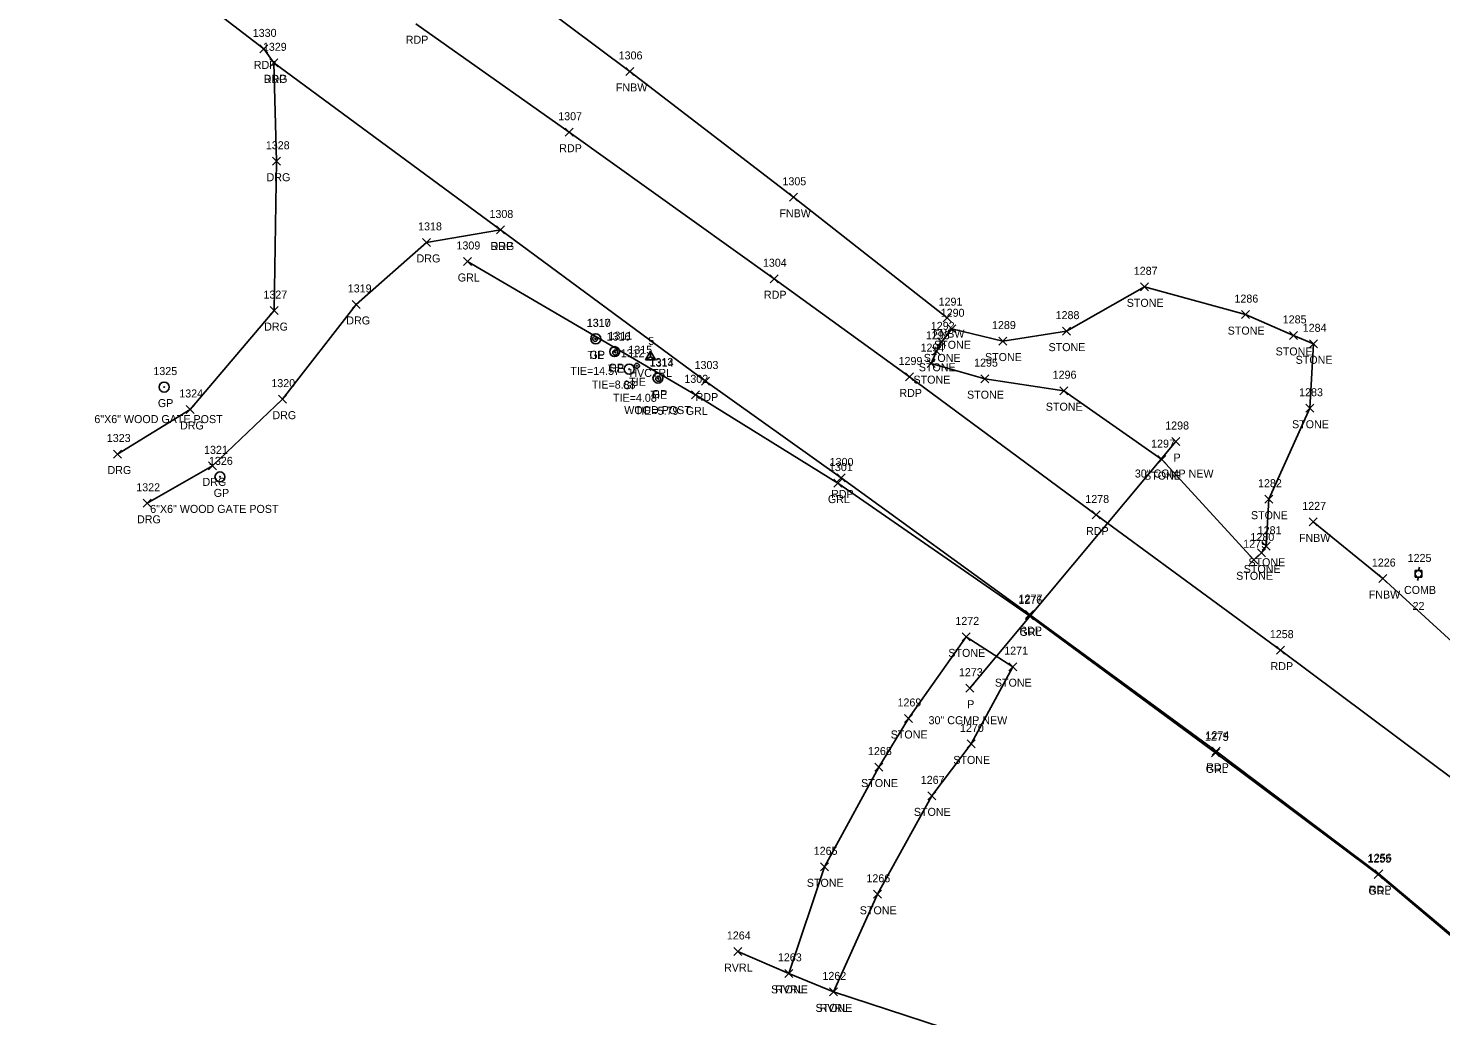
# Model space of a CAD drawing. Extents: x 1503463 to 1505240, y 712171 to 717196.
# Drawn here: x 1503951.4 to 1504304.4, y 715100.2 to 715346.9 of the extents above; entities that cross this region are included whole.
import ezdxf

# ---------------------------------------------------------------- set-up
doc = ezdxf.new("R2010")
doc.units = 0
for name, color, linetype in [('C_A', 7, 'Continuous'), ('C_C', 7, 'Continuous'), ('C_I', 7, 'Continuous'), ('CBP', 7, 'Continuous'), ('CPSM', 7, 'Continuous'), ('D_A', 7, 'Continuous'), ('D_C', 7, 'Continuous'), ('D_I', 7, 'Continuous'), ('D_TIC', 7, 'Continuous'), ('DCP', 7, 'Continuous'), ('L_A', 7, 'Continuous'), ('L_I', 7, 'Continuous'), ('L_TIC', 7, 'Continuous'), ('LASF', 7, 'Continuous'), ('LAWE', 7, 'Continuous'), ('LFNC', 7, 'Continuous'), ('P_A', 7, 'Continuous'), ('P_I', 7, 'Continuous'), ('P_TIC', 7, 'Continuous'), ('PET', 7, 'Continuous'), ('R_A', 7, 'Continuous'), ('R_C', 7, 'Continuous'), ('R_I', 7, 'Continuous'), ('R_TIC', 7, 'Continuous'), ('RDG', 7, 'Continuous'), ('RGP', 7, 'Continuous'), ('RGR', 7, 'Continuous'), ('U_A', 7, 'Continuous'), ('U_C', 7, 'Continuous'), ('U_I', 7, 'Continuous'), ('UP', 7, 'Continuous')]:
    doc.layers.add(name, color=color, linetype=linetype)

msp = doc.modelspace()

# ---------------------------------------------------------------- linework, layer by layer
at = {"layer": 'CBP'}
for centre, radius in [((1504093.06, 715269.34), 0.625), ((1504093.06, 715269.34), 0.0833), ((1504098.1, 715265.92), 0.625), ((1504098.1, 715265.92), 0.0833), ((1504103.49, 715262.61), 0.625), ((1504103.49, 715262.61), 0.0833), ((1504108.84, 715259.36), 0.625), ((1504108.84, 715259.36), 0.0833)]:
    msp.add_circle(centre, radius, dxfattribs=at)
at = {"layer": 'CPSM'}
for p, q in [((1504105.67, 715264.1), (1504106.92, 715266.27)), ((1504105.67, 715264.1), (1504106.92, 715264.82)), ((1504105.67, 715264.1), (1504108.17, 715264.1)), ((1504108.17, 715264.1), (1504106.92, 715266.27)), ((1504106.92, 715264.82), (1504106.92, 715266.27)), ((1504106.92, 715264.82), (1504106.92, 715264.82)), ((1504106.92, 715264.82), (1504108.17, 715264.1))]:
    msp.add_line(p, q, dxfattribs=at)
at = {"layer": 'D_TIC'}
for points in [[(1504237.24, 715242.69), (1504239.24, 715244.69)], [(1504239.24, 715242.69), (1504237.24, 715244.69)], [(1504185.69, 715181.05), (1504187.69, 715183.05)], [(1504187.69, 715181.05), (1504185.69, 715183.05)]]:
    msp.add_lwpolyline(points, dxfattribs=at)
at = {"layer": 'DCP'}
msp.add_lwpolyline([(1504186.69, 715182.05), (1504238.24, 715243.69)], dxfattribs=at)
at = {"layer": 'L_TIC'}
for points in [[(1504100.77, 715335.16), (1504102.77, 715337.16)], [(1504102.77, 715335.16), (1504100.77, 715337.16)], [(1504141.65, 715303.71), (1504143.65, 715305.71)], [(1504143.65, 715303.71), (1504141.65, 715305.71)], [(1504229.38, 715281.34), (1504231.38, 715283.34)], [(1504231.38, 715281.34), (1504229.38, 715283.34)], [(1504180.03, 715273.63), (1504182.03, 715275.63)], [(1504182.03, 715273.63), (1504180.03, 715275.63)], [(1504254.61, 715274.4), (1504256.61, 715276.4)], [(1504256.61, 715274.4), (1504254.61, 715276.4)], [(1504181.22, 715270.86), (1504183.22, 715272.86)], [(1504183.22, 715270.86), (1504181.22, 715272.86)], [(1504209.85, 715270.27), (1504211.85, 715272.27)], [(1504211.85, 715270.27), (1504209.85, 715272.27)], [(1504266.61, 715269.2), (1504268.61, 715271.2)], [(1504268.61, 715269.2), (1504266.61, 715271.2)], [(1504177.42, 715265.24), (1504179.42, 715267.24)], [(1504179.42, 715265.24), (1504177.42, 715267.24)], [(1504178.65, 715267.58), (1504180.65, 715269.58)], [(1504180.65, 715267.58), (1504178.65, 715269.58)], [(1504193.96, 715267.79), (1504195.96, 715269.79)], [(1504195.96, 715267.79), (1504193.96, 715269.79)], [(1504271.61, 715267.1), (1504273.61, 715269.1)], [(1504273.61, 715267.1), (1504271.61, 715269.1)], [(1504176.09, 715262.15), (1504178.09, 715264.15)], [(1504178.09, 715262.15), (1504176.09, 715264.15)], [(1504189.48, 715258.39), (1504191.48, 715260.39)], [(1504191.48, 715258.39), (1504189.48, 715260.39)], [(1504209.17, 715255.38), (1504211.17, 715257.38)], [(1504211.17, 715255.38), (1504209.17, 715257.38)], [(1504270.71, 715251), (1504272.71, 715253)], [(1504272.71, 715251), (1504270.71, 715253)], [(1504233.72, 715238.16), (1504235.72, 715240.16)], [(1504235.72, 715238.16), (1504233.72, 715240.16)], [(1504233.72, 715238.16), (1504235.72, 715240.16)], [(1504235.72, 715238.16), (1504233.72, 715240.16)], [(1504260.44, 715228.28), (1504262.44, 715230.28)], [(1504262.44, 715228.28), (1504260.44, 715230.28)], [(1504271.51, 715222.61), (1504273.51, 715224.61)], [(1504273.51, 715222.61), (1504271.51, 715224.61)], [(1504259.79, 715216.52), (1504261.79, 715218.52)], [(1504261.79, 715216.52), (1504259.79, 715218.52)], [(1504256.74, 715213.14), (1504258.74, 715215.14)], [(1504258.74, 715213.14), (1504256.74, 715215.14)], [(1504256.74, 715213.14), (1504258.74, 715215.14)], [(1504258.74, 715213.14), (1504256.74, 715215.14)], [(1504258.64, 715214.84), (1504260.64, 715216.84)], [(1504260.64, 715214.84), (1504258.64, 715216.84)], [(1504288.94, 715208.45), (1504290.94, 715210.45)], [(1504290.94, 715208.45), (1504288.94, 715210.45)], [(1504184.8, 715193.87), (1504186.8, 715195.87)], [(1504186.8, 715193.87), (1504184.8, 715195.87)], [(1504184.8, 715193.87), (1504186.8, 715195.87)], [(1504186.8, 715193.87), (1504184.8, 715195.87)], [(1504196.44, 715186.43), (1504198.44, 715188.43)], [(1504198.44, 715186.43), (1504196.44, 715188.43)], [(1504170.38, 715173.49), (1504172.38, 715175.49)], [(1504172.38, 715173.49), (1504170.38, 715175.49)], [(1504186.04, 715167.13), (1504188.04, 715169.13)], [(1504188.04, 715167.13), (1504186.04, 715169.13)], [(1504163, 715161.35), (1504165, 715163.35)], [(1504165, 715161.35), (1504163, 715163.35)], [(1504176.19, 715154.15), (1504178.19, 715156.15)], [(1504178.19, 715154.15), (1504176.19, 715156.15)], [(1504149.43, 715136.42), (1504151.43, 715138.42)], [(1504151.43, 715136.42), (1504149.43, 715138.42)], [(1504162.66, 715129.56), (1504164.66, 715131.56)], [(1504164.66, 715129.56), (1504162.66, 715131.56)], [(1504127.72, 715115.26), (1504129.72, 715117.26)], [(1504129.72, 715115.26), (1504127.72, 715117.26)], [(1504140.48, 715109.8), (1504142.48, 715111.8)], [(1504142.48, 715109.8), (1504140.48, 715111.8)], [(1504140.48, 715109.8), (1504142.48, 715111.8)], [(1504142.48, 715109.8), (1504140.48, 715111.8)], [(1504151.61, 715105.17), (1504153.61, 715107.17)], [(1504153.61, 715105.17), (1504151.61, 715107.17)], [(1504151.61, 715105.17), (1504153.61, 715107.17)], [(1504153.61, 715105.17), (1504151.61, 715107.17)]]:
    msp.add_lwpolyline(points, dxfattribs=at)
at = {"layer": 'LASF'}
for points in [[(1504257.74, 715214.14), (1504259.64, 715215.84), (1504260.79, 715217.52), (1504261.44, 715229.28), (1504271.71, 715252), (1504272.61, 715268.1), (1504267.61, 715270.2), (1504255.61, 715275.4), (1504230.38, 715282.34), (1504210.85, 715271.27), (1504194.96, 715268.79), (1504182.22, 715271.86), (1504179.65, 715268.58), (1504178.42, 715266.24), (1504177.09, 715263.15), (1504190.48, 715259.39), (1504210.17, 715256.38), (1504234.72, 715239.16)], [(1504257.74, 715214.14), (1504234.72, 715239.16)], [(1504141.48, 715110.8), (1504150.43, 715137.42), (1504164, 715162.35), (1504171.38, 715174.49), (1504185.8, 715194.87)], [(1504152.61, 715106.17), (1504163.66, 715130.56), (1504177.19, 715155.15), (1504187.04, 715168.13), (1504197.44, 715187.43), (1504185.8, 715194.87)]]:
    msp.add_lwpolyline(points, dxfattribs=at)
at = {"layer": 'LAWE'}
msp.add_lwpolyline([(1504428.01, 714856.32), (1504405.57, 714893.54), (1504378.11, 714927.51), (1504347.53, 714961.21), (1504311.78, 715002.92), (1504271.16, 715045.67), (1504223.13, 715076), (1504189.07, 715094.24), (1504152.61, 715106.17), (1504141.48, 715110.8), (1504128.72, 715116.26)], dxfattribs=at)
at = {"layer": 'LFNC'}
for points in [[(1504181.03, 715274.63), (1504142.65, 715304.71), (1504101.77, 715336.16), (1504063.51, 715364.82), (1504042.83, 715378.65)], [(1504574.09, 714914.16), (1504555.66, 714950.38), (1504537.29, 714983.75), (1504525.24, 715002.94), (1504507.14, 715023.01), (1504480.75, 715051.19), (1504465.15, 715069.97), (1504427.46, 715093.92), (1504393.83, 715121.36), (1504359.79, 715149.8), (1504312.1, 715189.24), (1504289.94, 715209.45), (1504272.51, 715223.61)]]:
    msp.add_lwpolyline(points, dxfattribs=at)
at = {"layer": 'P_TIC'}
for points in [[(1504009.26, 715340.79), (1504011.26, 715342.79)], [(1504011.26, 715340.79), (1504009.26, 715342.79)], [(1504011.71, 715337.31), (1504013.71, 715339.31)], [(1504013.71, 715337.31), (1504011.71, 715339.31)], [(1504085.6, 715319.97), (1504087.6, 715321.97)], [(1504087.6, 715319.97), (1504085.6, 715321.97)], [(1504068.42, 715295.54), (1504070.42, 715297.54)], [(1504070.42, 715295.54), (1504068.42, 715297.54)], [(1504136.77, 715283.36), (1504138.77, 715285.36)], [(1504138.77, 715283.36), (1504136.77, 715285.36)], [(1504170.61, 715258.82), (1504172.61, 715260.82)], [(1504172.61, 715258.82), (1504170.61, 715260.82)], [(1504119.68, 715257.8), (1504121.68, 715259.8)], [(1504121.68, 715257.8), (1504119.68, 715259.8)], [(1504153.53, 715233.59), (1504155.53, 715235.59)], [(1504155.53, 715233.59), (1504153.53, 715235.59)], [(1504217.27, 715224.33), (1504219.27, 715226.33)], [(1504219.27, 715224.33), (1504217.27, 715226.33)], [(1504200.61, 715199.45), (1504202.61, 715201.45)], [(1504202.61, 715199.45), (1504200.61, 715201.45)], [(1504263.39, 715190.56), (1504265.39, 715192.56)], [(1504265.39, 715190.56), (1504263.39, 715192.56)], [(1504247.31, 715165.3), (1504249.31, 715167.3)], [(1504249.31, 715165.3), (1504247.31, 715167.3)], [(1504287.97, 715134.69), (1504289.97, 715136.69)], [(1504289.97, 715134.69), (1504287.97, 715136.69)]]:
    msp.add_lwpolyline(points, dxfattribs=at)
at = {"layer": 'PET'}
for points in [[(1504628.86, 714571.69), (1504621.33, 714603.22), (1504611.21, 714644.87), (1504597.35, 714691.39), (1504582.78, 714732.74), (1504571.53, 714760.83), (1504551.13, 714806.83), (1504531.24, 714845.96), (1504513.33, 714878.02), (1504484.92, 714923.88), (1504464.76, 714952.16), (1504434.64, 714992.6), (1504400.79, 715031.63), (1504363.93, 715069.91), (1504326.41, 715104.24), (1504288.97, 715135.69), (1504248.31, 715166.3), (1504201.61, 715200.45), (1504154.53, 715234.59), (1504120.68, 715258.8), (1504069.42, 715296.54), (1504012.71, 715338.31), (1504010.26, 715341.79), (1503951.37, 715387.03)], [(1504657.14, 714577.6), (1504649.31, 714613.48), (1504639.83, 714651.58), (1504624, 714703.83), (1504610.47, 714743.63), (1504599.62, 714771.44), (1504577.65, 714820.8), (1504557.24, 714860.24), (1504539.4, 714891.39), (1504508.82, 714940.05), (1504488.73, 714969.22), (1504457.88, 715009.77), (1504422.56, 715051.33), (1504384.13, 715091.33), (1504346.68, 715126.54), (1504308.22, 715158.84), (1504264.39, 715191.56), (1504218.27, 715225.33), (1504171.61, 715259.82), (1504137.77, 715284.36), (1504086.6, 715320.97), (1504048.23, 715348.08)]]:
    msp.add_lwpolyline(points, dxfattribs=at)
at = {"layer": 'R_TIC'}
for points in [[(1504011.71, 715337.31), (1504013.71, 715339.31)], [(1504013.71, 715337.31), (1504011.71, 715339.31)], [(1504012.44, 715312.72), (1504014.44, 715314.72)], [(1504014.44, 715312.72), (1504012.44, 715314.72)], [(1504068.42, 715295.54), (1504070.42, 715297.54)], [(1504070.42, 715295.54), (1504068.42, 715297.54)], [(1504049.93, 715292.44), (1504051.93, 715294.44)], [(1504051.93, 715292.44), (1504049.93, 715294.44)], [(1504060.18, 715287.67), (1504062.18, 715289.67)], [(1504062.18, 715287.67), (1504060.18, 715289.67)], [(1504032.37, 715276.94), (1504034.37, 715278.94)], [(1504034.37, 715276.94), (1504032.37, 715278.94)], [(1504011.84, 715275.4), (1504013.84, 715277.4)], [(1504013.84, 715275.4), (1504011.84, 715277.4)], [(1504117.14, 715254.35), (1504119.14, 715256.35)], [(1504119.14, 715254.35), (1504117.14, 715256.35)], [(1504013.91, 715253.27), (1504015.91, 715255.27)], [(1504015.91, 715253.27), (1504013.91, 715255.27)], [(1503990.81, 715250.7), (1503992.81, 715252.7)], [(1503992.81, 715250.7), (1503990.81, 715252.7)], [(1503972.69, 715239.56), (1503974.69, 715241.56)], [(1503974.69, 715239.56), (1503972.69, 715241.56)], [(1503996.43, 715236.61), (1503998.43, 715238.61)], [(1503998.43, 715236.61), (1503996.43, 715238.61)], [(1504152.7, 715232.3), (1504154.7, 715234.3)], [(1504154.7, 715232.3), (1504152.7, 715234.3)], [(1503980.06, 715227.25), (1503982.06, 715229.25)], [(1503982.06, 715227.25), (1503980.06, 715229.25)], [(1504200.6, 715199.12), (1504202.6, 715201.12)], [(1504202.6, 715199.12), (1504200.6, 715201.12)], [(1504247.14, 715164.9), (1504249.14, 715166.9)], [(1504249.14, 715164.9), (1504247.14, 715166.9)], [(1504287.79, 715134.46), (1504289.79, 715136.46)], [(1504289.79, 715134.46), (1504287.79, 715136.46)]]:
    msp.add_lwpolyline(points, dxfattribs=at)
at = {"layer": 'RDG'}
for points in [[(1503973.69, 715240.56), (1503991.81, 715251.7), (1504012.84, 715276.4), (1504013.44, 715313.72), (1504012.71, 715338.31)], [(1504069.42, 715296.54), (1504050.93, 715293.44), (1504033.37, 715277.94), (1504014.91, 715254.27), (1503997.43, 715237.61), (1503981.06, 715228.25)]]:
    msp.add_lwpolyline(points, dxfattribs=at)
at = {"layer": 'RGP'}
for p, q in [((1504093.22, 715269.35), (1504093.22, 715269.35)), ((1504097.95, 715266.14), (1504097.95, 715266.14)), ((1504101.58, 715261.76), (1504101.58, 715261.76)), ((1503985.33, 715257.29), (1503985.33, 715257.29)), ((1504108.76, 715259.54), (1504108.76, 715259.54)), ((1503999.29, 715234.85), (1503999.29, 715234.85))]:
    msp.add_line(p, q, dxfattribs=at)
for centre, radius in [((1504093.22, 715269.35), 1.25), ((1504093.22, 715269.35), 0.0833), ((1504097.95, 715266.14), 1.25), ((1504097.95, 715266.14), 0.0833), ((1504101.58, 715261.76), 1.25), ((1504101.58, 715261.76), 0.0833), ((1504108.76, 715259.54), 1.25), ((1503985.33, 715257.29), 1.25), ((1503985.33, 715257.29), 0.0833), ((1504108.76, 715259.54), 0.0833), ((1503999.29, 715234.85), 1.25), ((1503999.29, 715234.85), 0.0833)]:
    msp.add_circle(centre, radius, dxfattribs=at)
at = {"layer": 'RGR'}
msp.add_lwpolyline([(1504616.71, 714600.2), (1504618.77, 714605.75), (1504618.48, 714611.67), (1504610.41, 714644.61), (1504596.35, 714690.53), (1504582.15, 714732.64), (1504570.9, 714760.4), (1504550.39, 714806.66), (1504530.74, 714845.7), (1504512.79, 714877.73), (1504484.33, 714923.22), (1504464.3, 714951.66), (1504433.51, 714991.73), (1504399.75, 715031.08), (1504363.28, 715069.4), (1504326.1, 715103.99), (1504288.79, 715135.46), (1504248.14, 715165.9), (1504201.6, 715200.12), (1504153.7, 715233.3), (1504118.14, 715255.35), (1504061.18, 715288.67)], dxfattribs=at)
at = {"layer": 'UP'}
for p, q in [((1504298.01, 715209.77), (1504298.01, 715211.43)), ((1504298.01, 715211.43), (1504299.68, 715211.43)), ((1504299.1, 715212.27), (1504298.85, 715211.43)), ((1504298.85, 715210.6), (1504298.85, 715210.6)), ((1504299.68, 715211.43), (1504299.68, 715209.77)), ((1504299.68, 715209.77), (1504298.01, 715209.77)), ((1504298.6, 715208.93), (1504298.85, 715209.77))]:
    msp.add_line(p, q, dxfattribs=at)
msp.add_circle((1504298.85, 715210.6), 0.833, dxfattribs=at)

# ---------------------------------------------------------------- texts
at = {"layer": 'C_A'}
for s, p in [('TIE', (1504091.14, 715264.34)), ('TIE', (1504096.18, 715260.92)), ('HVCTRL', (1504101.61, 715259.82)), ('TIE', (1504101.57, 715257.61)), ('TIE', (1504106.92, 715254.36))]:
    msp.add_text(s, height=2, dxfattribs=at).set_placement(p)
at = {"layer": 'C_C'}
for s, p in [('TIE=14.57', (1504086.86, 715260.34)), ('TIE=8.88', (1504092.23, 715256.92)), ('TIE=4.08', (1504097.53, 715253.61)), ('TIE=5.79', (1504102.96, 715250.36))]:
    msp.add_text(s, height=2, dxfattribs=at).set_placement(p)
at = {"layer": 'C_I'}
for s, p in [('1317', (1504090.94, 715272.34)), ('1316', (1504095.92, 715268.92)), ('1315', (1504101.36, 715265.61)), ('5', (1504106.36, 715267.82)), ('1314', (1504106.72, 715262.36))]:
    msp.add_text(s, height=2, dxfattribs=at).set_placement(p)
at = {"layer": 'D_A'}
for p in [(1504237.62, 715238.69), (1504186.06, 715177.05)]:
    msp.add_text('P', height=2, dxfattribs=at).set_placement(p)
at = {"layer": 'D_C'}
for p in [(1504227.96, 715234.69), (1504176.4, 715173.05)]:
    msp.add_text('30" CGMP NEW', height=2, dxfattribs=at).set_placement(p)
at = {"layer": 'D_I'}
for s, p in [('1298', (1504235.55, 715246.69)), ('1273', (1504183.99, 715185.05))]:
    msp.add_text(s, height=2, dxfattribs=at).set_placement(p)
at = {"layer": 'L_A'}
for s, p in [('FNBW', (1504098.24, 715331.16)), ('FNBW', (1504139.12, 715299.71)), ('STONE', (1504225.93, 715277.34)), ('FNBW', (1504177.51, 715269.63)), ('STONE', (1504251.16, 715270.4)), ('STONE', (1504177.77, 715266.86)), ('STONE', (1504206.39, 715266.27)), ('STONE', (1504263.15, 715265.2)), ('STONE', (1504175.19, 715263.58)), ('STONE', (1504190.5, 715263.79)), ('STONE', (1504268.15, 715263.1)), ('STONE', (1504172.63, 715258.15)), ('STONE', (1504173.96, 715261.24)), ('STONE', (1504186.02, 715254.39)), ('STONE', (1504205.71, 715251.38)), ('STONE', (1504267.25, 715247)), ('STONE', (1504230.27, 715234.16)), ('STONE', (1504230.27, 715234.16)), ('STONE', (1504256.98, 715224.28)), ('FNBW', (1504268.98, 715218.61)), ('STONE', (1504256.34, 715212.52)), ('STONE', (1504253.29, 715209.14)), ('STONE', (1504253.29, 715209.14)), ('STONE', (1504255.18, 715210.84)), ('FNBW', (1504286.42, 715204.45)), ('STONE', (1504181.34, 715189.87)), ('STONE', (1504181.34, 715189.87)), ('STONE', (1504192.98, 715182.43)), ('STONE', (1504166.93, 715169.49)), ('STONE', (1504182.58, 715163.13)), ('STONE', (1504159.54, 715157.35)), ('STONE', (1504172.73, 715150.15)), ('STONE', (1504145.97, 715132.42)), ('STONE', (1504159.21, 715125.56)), ('RVRL', (1504125.28, 715111.26)), ('STONE', (1504137.02, 715105.8)), ('RVRL', (1504138.04, 715105.8)), ('STONE', (1504148.15, 715101.17)), ('RVRL', (1504149.17, 715101.17))]:
    msp.add_text(s, height=2, dxfattribs=at).set_placement(p)
at = {"layer": 'L_I'}
for s, p in [('1306', (1504098.94, 715339.16)), ('1305', (1504139.88, 715307.71)), ('1287', (1504227.69, 715285.34)), ('1291', (1504178.91, 715277.63)), ('1286', (1504252.86, 715278.4)), ('1290', (1504179.44, 715274.86)), ('1288', (1504208.16, 715274.27)), ('1285', (1504264.92, 715273.2)), ('1293', (1504175.73, 715269.24)), ('1292', (1504176.96, 715271.58)), ('1289', (1504192.26, 715271.79)), ('1284', (1504269.92, 715271.1)), ('1294', (1504174.4, 715266.15)), ('1295', (1504187.78, 715262.39)), ('1296', (1504207.42, 715259.38)), ('1283', (1504269.02, 715255)), ('1297', (1504232.03, 715242.16)), ('1297', (1504232.03, 715242.16)), ('1282', (1504258.75, 715232.28)), ('1227', (1504269.81, 715226.61)), ('1281', (1504258.67, 715220.52)), ('1279', (1504255.04, 715217.14)), ('1279', (1504255.04, 715217.14)), ('1280', (1504256.86, 715218.84)), ('1226', (1504287.2, 715212.45)), ('1272', (1504183.1, 715197.87)), ('1272', (1504183.1, 715197.87)), ('1271', (1504195.31, 715190.43)), ('1269', (1504168.64, 715177.49)), ('1270', (1504184.26, 715171.13)), ('1268', (1504161.26, 715165.35)), ('1267', (1504174.45, 715158.15)), ('1265', (1504147.69, 715140.42)), ('1266', (1504160.87, 715133.56)), ('1264', (1504125.98, 715119.26)), ('1263', (1504138.74, 715113.8)), ('1263', (1504138.74, 715113.8)), ('1262', (1504149.87, 715109.17)), ('1262', (1504149.87, 715109.17))]:
    msp.add_text(s, height=2, dxfattribs=at).set_placement(p)
at = {"layer": 'P_A'}
for p in [(1504045.72, 715343.08), (1504007.75, 715336.79), (1504010.2, 715333.31), (1504084.09, 715315.97), (1504066.91, 715291.54), (1504135.25, 715279.36), (1504169.1, 715254.82), (1504118.17, 715253.8), (1504152.02, 715229.59), (1504215.76, 715220.33), (1504199.09, 715195.45), (1504261.88, 715186.56), (1504245.8, 715161.3), (1504286.46, 715130.69)]:
    msp.add_text('RDP', height=2, dxfattribs=at).set_placement(p)
at = {"layer": 'P_I'}
for s, p in [('1330', (1504007.48, 715344.79)), ('1329', (1504010.01, 715341.31)), ('1307', (1504083.83, 715323.97)), ('1308', (1504066.65, 715299.54)), ('1304', (1504134.99, 715287.36)), ('1303', (1504117.91, 715261.8)), ('1299', (1504168.91, 715262.82)), ('1300', (1504151.68, 715237.59)), ('1278', (1504215.58, 715228.33)), ('1277', (1504198.91, 715203.45)), ('1258', (1504261.7, 715194.56)), ('1274', (1504245.62, 715169.3)), ('1256', (1504286.23, 715138.69))]:
    msp.add_text(s, height=2, dxfattribs=at).set_placement(p)
at = {"layer": 'R_A'}
for s, p in [('DRG', (1504010.2, 715333.31)), ('DRG', (1504010.93, 715308.72)), ('DRG', (1504066.91, 715291.54)), ('DRG', (1504048.42, 715288.44)), ('GRL', (1504058.72, 715283.67)), ('DRG', (1504030.86, 715272.94)), ('DRG', (1504010.33, 715271.4)), ('GP', (1504091.65, 715264.35)), ('GP', (1504096.38, 715261.14)), ('GP', (1504100.01, 715256.76)), ('GP', (1504107.2, 715254.54)), ('GP', (1503983.77, 715252.29)), ('DRG', (1504012.4, 715249.27)), ('GRL', (1504115.69, 715250.35)), ('DRG', (1503989.3, 715246.7)), ('DRG', (1503971.18, 715235.56)), ('DRG', (1503994.92, 715232.61)), ('GP', (1503997.72, 715229.85)), ('GRL', (1504151.24, 715228.3)), ('DRG', (1503978.55, 715223.25)), ('GRL', (1504199.14, 715195.12)), ('GRL', (1504245.68, 715160.9)), ('GRL', (1504286.33, 715130.46))]:
    msp.add_text(s, height=2, dxfattribs=at).set_placement(p)
at = {"layer": 'R_C'}
for s, p in [('6"X6" WOOD GATE POST', (1503967.89, 715248.29)), ('WOOD POST', (1504100.33, 715250.54)), ('6"X6" WOOD GATE POST', (1503981.85, 715225.85))]:
    msp.add_text(s, height=2, dxfattribs=at).set_placement(p)
at = {"layer": 'R_I'}
for s, p in [('1329', (1504010.01, 715341.31)), ('1328', (1504010.75, 715316.72)), ('1308', (1504066.65, 715299.54)), ('1318', (1504048.81, 715296.44)), ('1309', (1504058.4, 715291.67)), ('1327', (1504010.15, 715279.4)), ('1319', (1504031.23, 715280.94)), ('1310', (1504091.01, 715272.35)), ('1311', (1504096.39, 715269.14)), ('1312', (1504099.46, 715264.76)), ('1313', (1504106.64, 715262.54)), ('1325', (1503982.64, 715260.29)), ('1302', (1504115.37, 715258.35)), ('1324', (1503989.12, 715254.7)), ('1320', (1504012.13, 715257.27)), ('1323', (1503971, 715243.56)), ('1321', (1503995.31, 715240.61)), ('1326', (1503996.54, 715237.85)), ('1301', (1504151.49, 715236.3)), ('1322', (1503978.37, 715231.25)), ('1276', (1504198.85, 715203.12)), ('1275', (1504245.45, 715168.9)), ('1255', (1504286.1, 715138.46))]:
    msp.add_text(s, height=2, dxfattribs=at).set_placement(p)
at = {"layer": 'U_A'}
msp.add_text('COMB', height=2, dxfattribs=at).set_placement((1504295.23, 715205.6))
at = {"layer": 'U_C'}
msp.add_text('22', height=2, dxfattribs=at).set_placement((1504297.38, 715201.6))
at = {"layer": 'U_I'}
msp.add_text('1225', height=2, dxfattribs=at).set_placement((1504296.15, 715213.6))

doc.saveas('drawing.dxf')
